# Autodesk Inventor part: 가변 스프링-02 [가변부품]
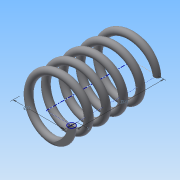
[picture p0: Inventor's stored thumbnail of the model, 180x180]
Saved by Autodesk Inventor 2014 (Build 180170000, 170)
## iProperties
Created: 2015-09
Part Number: 가변 스프링-02 [가변부품]
Material: 강철, 탄소
Document SubType Name: Modeling
Designer: study
Density: 1 g/cm^3
Appearance: 반연마
Author: study
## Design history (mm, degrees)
sketch "스케치1"
  geometry: L1 (0, 0)-(11, 0); L2 (11, 0)-(11, 25.358); L3 (11, 25.358)-(0, 25.358); L4 (0, 25.358)-(0, 0); C1 r 1.5 at (11, 0)
  constraints: 8 end point, 2 parallel, 1 centre point, 1 coincident, 1 horizontal, 1 perpendicular
  dimensions: "d0" = 3 diameter of C1; "d1" = 22 diameter of L2 L4; "d2" = 25.35829 distance of L1.end L2.end (derived)
feature "코일1" sketch "스케치1" pitch "d3" = 10; turns "d5" = 5; dims "d4" = 25.35829 (= d2), "d6" = 0, angle "d7" = 90 deg, angle "d8" = 90 deg, "d9" = 0, "d10" = 0
node "작업 평면1"
sketch "스케치2"
  geometry: L1 (-12.5, 0)-(-9.5, 0) reference; 1 further point
  constraints: 1 horizontal alignment
extrude "돌출1" cut sketch "스케치2" distance "d12" = 10; taper "d13" = 0 deg
node "작업 평면2"
sketch "스케치3"
  geometry: L1 (-9.5, 0)-(-12.5, 0) reference; L2 (-9.5, 0)-(-12.5, 0) reference; 1 further point
  constraints: 2 horizontal alignment
extrude "돌출2" cut sketch "스케치3" distance "d15" = 10; taper "d16" = 0 deg
node "솔리드1"
node "절단 모서리 투영1"
node "절단 모서리 투영2"
node "절단 모서리 투영3"
other parameters: "d11" = 0, "d14" = 25.35829 (= d2)
